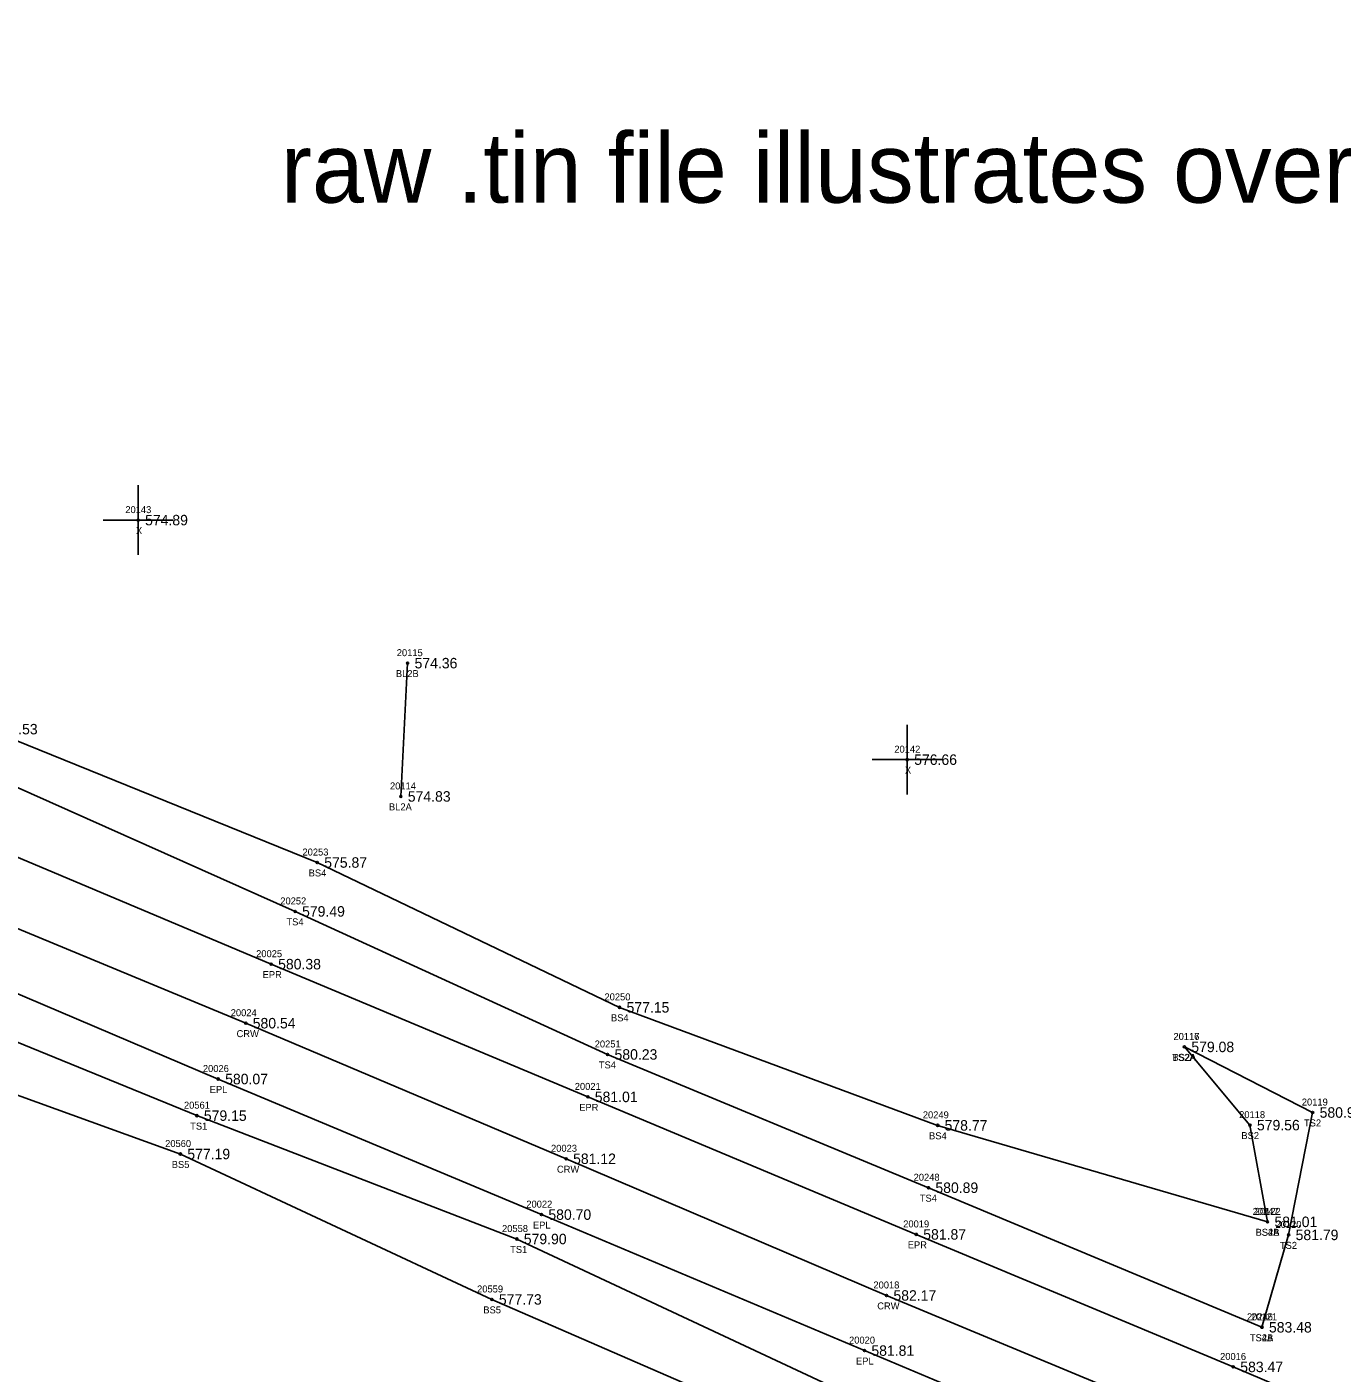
# Model space of a CAD drawing. Extents: x 1664837 to 1666270, y 987403 to 988245.
# Drawn here: x 1665759.5 to 1665947.9, y 987594.7 to 987787.6 of the extents above; entities that cross this region are included whole.
import ezdxf

# ---------------------------------------------------------------- set-up
doc = ezdxf.new("R2010")
doc.units = 0
for name, color, linetype in [('RD_DTM_BkLn1', 7, 'Continuous'), ('RD_DTM_BkLn2', 7, 'Continuous'), ('RD_DTM_BkLn_txCode', 7, 'Continuous'), ('RD_DTM_Tri2', 7, 'Continuous'), ('RD_EX_Misc', 7, 'Continuous'), ('RD_EX_Misc_txCode', 7, 'Continuous'), ('RD_EX_Road', 7, 'Continuous'), ('RD_EX_Road_txCode', 7, 'Continuous'), ('RD_EX_TX_Misc_ELEV', 7, 'Continuous'), ('RD_EX_TX_Road_ELEV', 7, 'Continuous'), ('RD_HC_Survey_ELEV', 7, 'Continuous'), ('RD_HC_Survey_txCode', 7, 'Continuous'), ('RD_SMD_Locator', 7, 'Continuous')]:
    doc.layers.add(name, color=color, linetype=linetype)

msp = doc.modelspace()

# ---------------------------------------------------------------- linework, layer by layer
at = {"layer": 'RD_DTM_BkLn1'}
msp.add_line((1665813.08, 987677.31), (1665814.05, 987696.41), dxfattribs=at)
msp.add_lwpolyline([(1666158.65, 987488.74), (1666112.69, 987508.17), (1666066.71, 987527.94), (1666020.54, 987547.08), (1665974.85, 987566.77), (1665928.96, 987586.52), (1665882.66, 987605.79), (1665836.76, 987625.38), (1665790.86, 987644.81), (1665744.75, 987663.93), (1665698.8, 987683.39), (1665652.93, 987702.82), (1665606.7, 987721.88), (1665561.04, 987742.04), (1665527.67, 987755.89)], dxfattribs=at)
at = {"layer": 'RD_DTM_BkLn2'}
for points in [[(1665937.25, 987616.34), (1665889.99, 987630.17), (1665844.42, 987647.08), (1665801.11, 987667.84), (1665753.91, 987686.95), (1665707.93, 987709.21), (1665661.99, 987726.38), (1665615.37, 987748.93), (1665567.93, 987769.01), (1665555.48, 987787.59)], [(1665936.46, 987601.23), (1665888.67, 987621.23), (1665842.7, 987640.33), (1665797.93, 987660.83), (1665752.01, 987681.29), (1665704.64, 987700.49), (1665658.36, 987719.6), (1665612.75, 987738.02), (1665564.88, 987757.28), (1665542.58, 987772.17), (1665532.86, 987767.81)], [(1666152.82, 987476.83), (1666108.53, 987496.54), (1666062.68, 987516.61), (1666015.91, 987535.8), (1665969.55, 987555.16), (1665926.09, 987572.12), (1665875.73, 987592.3), (1665829.7, 987613.88), (1665783.86, 987631.56), (1665738.66, 987650.04), (1665693.22, 987670.26), (1665645.99, 987690.14), (1665601.24, 987708.82), (1665555.03, 987727.9), (1665522.94, 987740.22)], [(1666117.29, 987404.85), (1666064.63, 987440.28), (1666022.87, 987464.18), (1665976.62, 987505.49), (1665934.85, 987514.58), (1665901.43, 987514.29), (1665891.04, 987542.26), (1665910.76, 987561.83), (1665873.03, 987584.83), (1665826.13, 987605.22), (1665781.49, 987626.06), (1665735.29, 987642.75), (1665690.09, 987662.74), (1665646.61, 987681.64)], [(1665925.34, 987641.41), (1665943.72, 987632.01), (1665940.28, 987614.47), (1665936.46, 987601.23)], [(1665925.34, 987641.41), (1665934.74, 987630.2), (1665937.25, 987616.34)]]:
    msp.add_lwpolyline(points, dxfattribs=at)
at = {"layer": 'RD_EX_Misc'}
for p, q in [((1665775.44, 987711.91), (1665775.44, 987721.91)), ((1665770.44, 987716.91), (1665780.44, 987716.91)), ((1665885.63, 987677.58), (1665885.63, 987687.58)), ((1665880.63, 987682.58), (1665890.63, 987682.58))]:
    msp.add_line(p, q, dxfattribs=at)
at = {"layer": 'RD_EX_Road'}
for points in [[(1666163.18, 987497.62), (1666116.6, 987517.39), (1666070.7, 987536.94), (1666024.42, 987556.43), (1665979.02, 987575.67), (1665932.35, 987595.55), (1665886.93, 987614.54), (1665839.87, 987634.25), (1665794.5, 987653.27), (1665748.81, 987672.51), (1665702.36, 987691.87), (1665656.42, 987711.45), (1665610.33, 987731.03), (1665564.85, 987750.93), (1665531.47, 987764.82)], [(1666156.67, 987480.61), (1666109.28, 987500.74), (1666063.55, 987520.04), (1666017.04, 987539.82), (1665971.11, 987559.14), (1665924.88, 987578.79), (1665879.5, 987597.89), (1665833.22, 987617.38), (1665786.91, 987636.81), (1665741.44, 987656.13), (1665695.81, 987675.2), (1665649.26, 987694.85), (1665603.56, 987714.71), (1665558.4, 987733.87), (1665524.71, 987748.93)]]:
    msp.add_lwpolyline(points, dxfattribs=at)
at = {"layer": 'RD_SMD_Locator'}
for centre in [(1665775.44, 987716.91), (1665814.05, 987696.41), (1665885.63, 987682.58), (1665813.08, 987677.31), (1665801.11, 987667.84), (1665797.93, 987660.83), (1665794.5, 987653.27), (1665844.42, 987647.08), (1665790.86, 987644.81), (1665842.7, 987640.33), (1665925.34, 987641.41), (1665925.34, 987641.41), (1665786.91, 987636.81), (1665839.87, 987634.25), (1665943.72, 987632.01), (1665783.86, 987631.56), (1665889.99, 987630.17), (1665934.74, 987630.2), (1665781.49, 987626.06), (1665836.76, 987625.38), (1665888.67, 987621.23), (1665833.22, 987617.38), (1665886.93, 987614.54), (1665937.25, 987616.34), (1665937.25, 987616.34), (1665940.28, 987614.47), (1665829.7, 987613.88), (1665826.13, 987605.22), (1665882.66, 987605.79), (1665936.46, 987601.23), (1665936.46, 987601.23), (1665879.5, 987597.89), (1665932.35, 987595.55)]:
    msp.add_circle(centre, 0.15, dxfattribs=at)

# ---------------------------------------------------------------- texts
at = {"layer": 'RD_DTM_BkLn_txCode'}
for s, p in [('20115', (1665812.5, 987697.41)), ('BL2B', (1665812.37, 987694.41)), ('20114', (1665811.53, 987678.31)), ('BL2A', (1665811.38, 987675.31)), ('20253', (1665798.99, 987668.84)), ('BS4', (1665799.88, 987665.84)), ('20252', (1665795.81, 987661.83)), ('TS4', (1665796.69, 987658.83)), ('20250', (1665842.26, 987648.08)), ('BS4', (1665843.19, 987645.08)), ('20251', (1665840.86, 987641.33)), ('20116', (1665923.77, 987642.41)), ('20117', (1665923.79, 987642.41)), ('TS2A', (1665923.61, 987639.41)), ('BS2A', (1665923.63, 987639.41)), ('TS4', (1665841.45, 987638.33)), ('20119', (1665942.17, 987633.01)), ('20561', (1665782.01, 987632.56)), ('20249', (1665887.87, 987631.17)), ('20118', (1665933.19, 987631.2)), ('TS1', (1665782.9, 987629.56)), ('TS2', (1665942.48, 987630.01)), ('20560', (1665779.31, 987627.06)), ('BS4', (1665888.76, 987628.17)), ('BS2', (1665933.51, 987628.2)), ('BS5', (1665780.26, 987624.06)), ('20248', (1665886.55, 987622.23)), ('TS4', (1665887.43, 987619.23)), ('20247', (1665935.13, 987617.34)), ('20122', (1665935.42, 987617.34)), ('20558', (1665827.58, 987614.88)), ('BS4A', (1665935.53, 987614.34)), ('BS2B', (1665935.55, 987614.34)), ('20120', (1665938.4, 987615.47)), ('TS1', (1665828.74, 987611.88)), ('TS2', (1665939.03, 987612.47)), ('20559', (1665824.01, 987606.22)), ('BS5', (1665824.9, 987603.22)), ('20246', (1665934.31, 987602.23)), ('20121', (1665934.9, 987602.23)), ('TS4A', (1665934.72, 987599.23)), ('TS2B', (1665934.74, 987599.23))]:
    msp.add_text(s, height=1, dxfattribs=at).set_placement(p)
at = {"layer": 'RD_DTM_Tri2'}
msp.add_text('raw .tin file illustrates overlap at pavement end at bridge and  top of bridge slope', height=10, dxfattribs=at).set_placement((1665795.89, 987762.4))
at = {"layer": 'RD_EX_Misc_txCode'}
for s, p in [('20143', (1665773.61, 987717.91)), ('X', (1665775.13, 987714.91)), ('20142', (1665883.79, 987683.58)), ('X', (1665885.31, 987680.58))]:
    msp.add_text(s, height=1, dxfattribs=at).set_placement(p)
at = {"layer": 'RD_EX_Road_txCode'}
for s, p in [('20025', (1665792.35, 987654.27)), ('EPR', (1665793.28, 987651.27)), ('20026', (1665784.72, 987637.81)), ('EPL', (1665785.7, 987634.81)), ('20021', (1665838, 987635.25)), ('EPR', (1665838.64, 987632.25)), ('20022', (1665831.06, 987618.38)), ('20019', (1665885.06, 987615.54)), ('EPL', (1665832.01, 987615.38)), ('EPR', (1665885.71, 987612.54)), ('20020', (1665877.3, 987598.89)), ('20016', (1665930.46, 987596.55)), ('EPL', (1665878.29, 987595.89))]:
    msp.add_text(s, height=1, dxfattribs=at).set_placement(p)
at = {"layer": 'RD_EX_TX_Misc_ELEV'}
for s, p in [('574.89', (1665776.44, 987716.16)), ('574.36', (1665815.05, 987695.66)), ('575.53', (1665754.91, 987686.2)), ('576.66', (1665886.63, 987681.83)), ('574.83', (1665814.08, 987676.56)), ('575.87', (1665802.11, 987667.09)), ('579.49', (1665798.93, 987660.08)), ('577.15', (1665845.42, 987646.33)), ('579.08', (1665926.34, 987640.66)), ('579.08', (1665926.34, 987640.66)), ('580.23', (1665843.7, 987639.58)), ('579.15', (1665784.86, 987630.81)), ('580.93', (1665944.72, 987631.26)), ('578.77', (1665890.99, 987629.42)), ('579.56', (1665935.74, 987629.45)), ('577.19', (1665782.49, 987625.31)), ('580.89', (1665889.67, 987620.48)), ('581.01', (1665938.25, 987615.59)), ('581.01', (1665938.25, 987615.59)), ('579.90', (1665830.7, 987613.13)), ('581.79', (1665941.28, 987613.72)), ('577.73', (1665827.13, 987604.47)), ('583.48', (1665937.46, 987600.48)), ('583.48', (1665937.46, 987600.48))]:
    msp.add_text(s, height=1.5, dxfattribs=at).set_placement(p)
at = {"layer": 'RD_EX_TX_Road_ELEV'}
for s, p in [('580.38', (1665795.5, 987652.52)), ('580.07', (1665787.91, 987636.06)), ('581.01', (1665840.87, 987633.5)), ('580.70', (1665834.22, 987616.63)), ('581.87', (1665887.93, 987613.79)), ('581.81', (1665880.5, 987597.14)), ('583.47', (1665933.35, 987594.8))]:
    msp.add_text(s, height=1.5, dxfattribs=at).set_placement(p)
at = {"layer": 'RD_HC_Survey_ELEV'}
for s, p in [('580.54', (1665791.86, 987644.06)), ('581.12', (1665837.76, 987624.63)), ('582.17', (1665883.66, 987605.04))]:
    msp.add_text(s, height=1.5, dxfattribs=at).set_placement(p)
at = {"layer": 'RD_HC_Survey_txCode'}
for s, p in [('20024', (1665788.71, 987645.81)), ('CRW', (1665789.55, 987642.81)), ('20023', (1665834.6, 987626.38)), ('CRW', (1665835.45, 987623.38)), ('20018', (1665880.79, 987606.79)), ('CRW', (1665881.34, 987603.79))]:
    msp.add_text(s, height=1, dxfattribs=at).set_placement(p)

doc.saveas('drawing.dxf')
